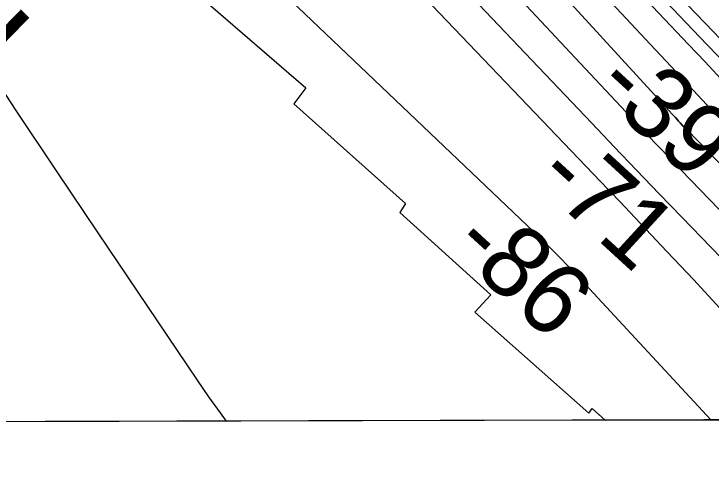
# Model space of a CAD drawing. Extents: x 3355677 to 3393573, y 612928 to 638357.
# Drawn here: x 3377478 to 3378130, y 618312 to 618740 of the extents above; entities that cross this region are included whole.
import ezdxf

# ---------------------------------------------------------------- set-up
doc = ezdxf.new("R2010")
doc.units = 0
for name, color, linetype in [('V-GRID-FRAM', 7, 'Continuous'), ('V-RIVR-EDGE', 7, 'Continuous'), ('V-RIVR-RANG', 7, 'Continuous'), ('V-RRAP-RVMT', 7, 'Continuous'), ('V-TOPO-DPTH', 7, 'Continuous'), ('V-TOPO-GNAM-IDEN', 7, 'Continuous'), ('V-TOPO-MAJR', 7, 'Continuous'), ('V-TOPO-MINR', 7, 'Continuous')]:
    doc.layers.add(name, color=color, linetype=linetype)

msp = doc.modelspace()

# ---------------------------------------------------------------- linework, layer by layer
at = {"layer": 'V-GRID-FRAM'}
msp.add_lwpolyline([(3359767.89, 636495.86), (3391341.63, 636578.52), (3391397.17, 618394.77), (3359807.56, 618312.07), (3359767.89, 636495.86)], dxfattribs=at)
at = {"layer": 'V-RIVR-EDGE'}
msp.add_spline([(3378516.49, 618361.05), (3378507.6, 618370.69), (3378490.73, 618386.23), (3378471.74, 618402.14), (3378446.08, 618427.92), (3378423.59, 618453.7), (3378402.15, 618477.72), (3378364.89, 618515.51), (3378349.43, 618530.35), (3378342.04, 618535.3), (3378334.65, 618539.2), (3378327.62, 618546.97), (3378322.71, 618554.38), (3378318.84, 618559.67), (3378306.54, 618572.39), (3378288.96, 618586.53), (3378281.23, 618596.41), (3378275.96, 618603.83), (3378258.04, 618621.84), (3378254.18, 618629.96), (3378247.86, 618638.78), (3378236.96, 618650.79), (3378233.81, 618657.14), (3378231.35, 618661.38), (3378222.57, 618670.56), (3378197.97, 618699.87), (3378183.21, 618714), (3378173.72, 618726.71), (3378162.47, 618734.49), (3378158.95, 618737.67), (3378158.61, 618741.54), (3378158.26, 618744.72), (3378155.81, 618749.66), (3378152.29, 618753.19), (3378146.31, 618755.67), (3378143.5, 618758.85), (3378140, 618769.43), (3378130.53, 618786.72), (3378121.05, 618799.43), (3378116.48, 618802.96), (3378111.54, 618803.33), (3378106.96, 618803.69), (3378107.68, 618808.27), (3378105.22, 618811.8), (3378096.08, 618818.87), (3378090.1, 618823.82), (3378078.84, 618830.54), (3378077.08, 618832.66), (3378071.83, 618844.3), (3378067.97, 618853.12), (3378067.98, 618856.29), (3378066.58, 618858.76), (3378058.13, 618863.01), (3378052.16, 618871.83), (3378044.1, 618888.77), (3378037.43, 618898.65), (3378027.59, 618911.01), (3378012.81, 618918.45), (3378000.84, 618924.11), (3377993.11, 618932.59), (3377988.55, 618941.06), (3377985.4, 618949.52), (3377982.24, 618954.46), (3377974.51, 618963.29), (3377969.24, 618967.89), (3377966.79, 618973.88), (3377960.81, 618977.77), (3377955.52, 618978.84), (3377954.83, 618983.07), (3377951.31, 618985.9), (3377937.58, 618991.22), (3377933.72, 618995.46), (3377918.25, 619012.76), (3377900.33, 619032.19), (3377899.99, 619037.47), (3377897.54, 619041.71), (3377893.67, 619045.59), (3377886.27, 619044.91), (3377882.39, 619044.92), (3377878.87, 619047.39), (3377875.72, 619053.74), (3377866.93, 619063.28), (3377843.02, 619083.78), (3377840.22, 619089.42), (3377839.18, 619096.12), (3377836.71, 619097.89), (3377833.19, 619098.25), (3377832.49, 619100.01), (3377831.44, 619103.89), (3377828.98, 619106.01), (3377820.18, 619110.97), (3377809.64, 619121.21), (3377795.58, 619135.69), (3377778.71, 619154.76), (3377773.79, 619160.41), (3377758.67, 619171.37), (3377751.64, 619178.79), (3377734.41, 619195.04), (3377715.08, 619215.53), (3377698.93, 619236.36), (3377689.44, 619246.6), (3377686.28, 619253.66), (3377675.73, 619259.67), (3377669.05, 619265.33), (3377666.24, 619269.92), (3377662.02, 619272.39), (3377656.38, 619274.17), (3377649.7, 619279.47), (3377628.6, 619296.08), (3377619.46, 619304.56), (3377610.32, 619314.45), (3377594.85, 619326.47), (3377585.71, 619336.01), (3377577.62, 619344.49), (3377561.44, 619355.45), (3377551.95, 619364.63), (3377544.22, 619374.17), (3377540.72, 619384.04), (3377539.32, 619385.81), (3377536.15, 619386.87), (3377528.75, 619389.01), (3377525.59, 619391.83), (3377523.49, 619398.53), (3377519.99, 619409.11), (3377509.1, 619421.12), (3377504.18, 619425.71), (3377489.74, 619431.04), (3377482.35, 619435.28), (3377478.49, 619440.93), (3377476.38, 619443.05), (3377471.46, 619446.94), (3377465.14, 619455.41), (3377463.39, 619460), (3377454.25, 619470.59), (3377432.47, 619495.66), (3377419.12, 619513.31), (3377396.28, 619540.15), (3377376.96, 619562.4), (3377360.09, 619581.12), (3377353.41, 619589.94), (3377348.5, 619598.76), (3377341.83, 619607.59), (3377323.55, 619623.49), (3377313.35, 619633.38), (3377305.61, 619638.33), (3377297.52, 619644.7), (3377297.53, 619647.87), (3377297.54, 619650.69), (3377294.03, 619656.69), (3377285.24, 619666.58), (3377279.28, 619677.16), (3377274.01, 619683.52), (3377265.56, 619688.47), (3377258.89, 619694.83), (3377253.62, 619705.06), (3377251.89, 619714.93), (3377248.03, 619720.93), (3377245.57, 619724.46), (3377241.7, 619727.64), (3377232.89, 619728.37), (3377223.38, 619730.86), (3377212.47, 619733.35), (3377204.37, 619737.6), (3377200.86, 619740.08), (3377195.22, 619741.15), (3377185.71, 619741.17), (3377172.33, 619748.61), (3377155.8, 619761.33), (3377143.16, 619778.28), (3377132.62, 619792.4), (3377131.93, 619797.33), (3377130.18, 619802.27), (3377123.51, 619811.1), (3377116.49, 619822.04), (3377110.17, 619832.98), (3377098.6, 619854.85), (3377095.09, 619862.97), (3377087.73, 619876.73), (3377081.41, 619884.85), (3377075.78, 619891.2), (3377063.5, 619909.91), (3377063.15, 619913.08), (3377058.59, 619921.55), (3377041.74, 619947.67), (3377035.78, 619957.9), (3377024.88, 619970.26), (3377017.51, 619982.26), (3377008.73, 619991.09), (3377000.99, 619999.22), (3376998.89, 620003.1), (3376997.85, 620008.39), (3376993.28, 620014.39), (3376981.69, 620029.57), (3376966.57, 620041.59), (3376947.93, 620056.08), (3376931.04, 620066.69), (3376914.5, 620075.54), (3376905.71, 620081.91), (3376896.22, 620095.67), (3376889.56, 620109.08), (3376877.63, 620128.14), (3376863.24, 620153.19), (3376850.61, 620175.78), (3376840.44, 620195.18), (3376834.13, 620206.12), (3376830.62, 620213.88), (3376827.11, 620219.88), (3376766.3, 620280.64), (3376733.96, 620311.73), (3376710.76, 620332.22), (3376680.51, 620356.61), (3376664.69, 620368.98), (3376652.37, 620376.06), (3376623.52, 620393.4), (3376605.58, 620405.78), (3376585.52, 620418.86), (3376578.14, 620424.17), (3376571.8, 620428.06), (3376565.46, 620427.02), (3376541.18, 620440.12), (3376536.96, 620446.47), (3376535.22, 620453.17), (3376537.71, 620461.97), (3376537.72, 620466.2), (3376535.61, 620469.03), (3376529.98, 620470.8), (3376523.63, 620470.11), (3376520.11, 620471.53), (3376509.21, 620481.07), (3376501.13, 620489.55), (3376495.52, 620499.78), (3376489.55, 620510.72), (3376487.1, 620514.95), (3376486.05, 620518.13), (3376484.29, 620520.6), (3376464.95, 620537.91), (3376449.83, 620547.47), (3376433.64, 620556.31), (3376408.32, 620577.17), (3376393.54, 620585.66), (3376376.29, 620593.81), (3376351.66, 620606.2), (3376335.11, 620613.29), (3376324.56, 620620.01), (3376307.31, 620625.34), (3376296.04, 620630.65), (3376270.36, 620648.34), (3376252.78, 620662.12), (3376242.94, 620672.72), (3376238.01, 620675.9), (3376233.43, 620676.62), (3376229.56, 620679.09), (3376210.93, 620695.35), (3376192.64, 620709.84), (3376157.47, 620736.71), (3376139.88, 620750.14), (3376127.93, 620761.8), (3376118.44, 620769.58), (3376106.12, 620776.3), (3376072.01, 620806.34), (3376048.47, 620834.23), (3376004.89, 620878.04), (3375983.1, 620902.76), (3375960.97, 620929.59), (3375953.95, 620939.83), (3375949.03, 620948.3), (3375944.83, 620957.82), (3375936.05, 620971.59), (3375912.87, 621001.6), (3375906.89, 621006.9), (3375899.52, 621016.43), (3375896.01, 621023.48), (3375881.26, 621042.55), (3375856.32, 621075.38), (3375835.59, 621097.28), (3375809.57, 621122.72), (3375786.01, 621142.15), (3375742.74, 621169.75), (3375706.5, 621193.09), (3375654.8, 621233.74), (3375605.57, 621273.68), (3375571.82, 621307.24), (3375559.88, 621321.37), (3375554.61, 621330.89), (3375550.75, 621336.89), (3375547.94, 621339.72), (3375541.25, 621342.56), (3375536.33, 621345.74), (3375533.51, 621347.86), (3375528.24, 621352.81), (3375524.03, 621359.16), (3375521.22, 621361.99), (3375518.76, 621365.16), (3375514.54, 621369.76), (3375499.05, 621375.43), (3375478.63, 621382.53), (3375451.52, 621393.17), (3375434.62, 621398.5), (3375424.77, 621404.51), (3375412.44, 621407.36), (3375405.76, 621410.55), (3375395.2, 621414.45), (3375385.69, 621417.29), (3375374.07, 621420.49), (3375363.5, 621420.87), (3375351.51, 621419.14), (3375336.69, 621411.07), (3375326.11, 621405.81), (3375315.54, 621405.48), (3375306.73, 621408.33), (3375297.58, 621412.93), (3375285.62, 621419.3), (3375281.41, 621425.65), (3375276.14, 621431.66), (3375271.91, 621433.78), (3375264.16, 621435.21), (3375259.93, 621435.22), (3375254.65, 621435.24), (3375251.48, 621435.24), (3375245.49, 621436.31), (3375239.86, 621437.74), (3375215.21, 621444.49), (3375187.39, 621452.67), (3375156.75, 621461.2), (3375150.77, 621464.74), (3375147.25, 621465.8), (3375142.67, 621466.87), (3375137.39, 621467.94), (3375132.1, 621468.31), (3375129.64, 621468.32), (3375105.35, 621477.18), (3375084.93, 621485.69), (3375080.36, 621489.23), (3375075.08, 621491.35), (3375067.33, 621492.43), (3375058.88, 621497.03), (3375037.06, 621506.95), (3374951.91, 621556.5), (3374890.69, 621595.76), (3374838.99, 621635), (3374815.41, 621649.51), (3374801.34, 621657.65)], degree=3, dxfattribs=at)
at = {"layer": 'V-RRAP-RVMT'}
for p, q in [((3377650.96, 618757.19), (3377750.73, 618670.87)), ((3377750.73, 618670.87), (3377739.48, 618655.88)), ((3377739.48, 618655.88), (3377843.97, 618562.35)), ((3377843.97, 618562.35), (3377838.68, 618553.91)), ((3377838.68, 618553.91), (3377923.74, 618477.13)), ((3377923.74, 618477.13), (3377908.82, 618460.92)), ((3377908.82, 618460.92), (3378015.57, 618366.23)), ((3378015.57, 618366.23), (3378018.72, 618370.53)), ((3378018.72, 618370.53), (3378030.91, 618359.78)), ((3378030.91, 618359.78), (3378546.23, 618361.13))]:
    msp.add_line(p, q, dxfattribs=at)
at = {"layer": 'V-TOPO-DPTH'}
for points in [[(3378476.02, 618360.94), (3378448.01, 618390.37), (3378375.02, 618467.18), (3378302.07, 618544.02), (3378204.39, 618646.98), (3378180.3, 618672.37), (3378156.2, 618697.74), (3378132.09, 618723.11), (3378107.97, 618748.46), (3378083.82, 618773.79), (3378059.62, 618799.07), (3378035.36, 618824.29), (3378011.06, 618849.47), (3377654.1, 619218.36), (3377630.45, 619242.73), (3377606.74, 619267.05), (3377582.95, 619291.29), (3377559.11, 619315.48), (3377535.23, 619339.63), (3377511.35, 619363.79), (3377487.48, 619387.94), (3377463.6, 619412.1), (3377132.12, 619747.52), (3377122.42, 619757.43)], [(3378369.48, 618360.66), (3378107.77, 618630.99), (3378105.54, 618633.31), (3378103.3, 618635.62), (3378100.96, 618638.07), (3378099.49, 618639.64), (3378098.71, 618640.5), (3378096.55, 618642.88), (3378093.62, 618646.11), (3378090.67, 618649.34), (3377711.84, 619063.27), (3377687.62, 619089.53), (3377663.27, 619115.66), (3377638.71, 619141.61), (3377614.03, 619167.43), (3377577.27, 619205.59), (3377570.84, 619212.22), (3377564.39, 619218.82), (3377557.9, 619225.39), (3377551.37, 619231.92), (3377089.65, 619691.99)], [(3377089.65, 619691.99), (3377551.37, 619231.92), (3377557.9, 619225.39), (3377564.39, 619218.82), (3377570.84, 619212.22), (3377577.27, 619205.59), (3377614.03, 619167.43), (3377638.71, 619141.61), (3377663.27, 619115.66), (3377687.62, 619089.53), (3377711.84, 619063.27), (3378090.67, 618649.34), (3378093.62, 618646.11), (3378096.55, 618642.88), (3378098.71, 618640.5), (3378099.49, 618639.64), (3378100.96, 618638.07), (3378103.3, 618635.62), (3378105.54, 618633.31), (3378107.77, 618630.99), (3378369.48, 618360.66)], [(3377298.46, 619514.44), (3377550.44, 619262.16), (3377564.24, 619248.26), (3377578, 619234.32), (3377591.68, 619220.31), (3377605.31, 619206.25), (3377683.76, 619124.9), (3377736.44, 619070), (3377788.94, 619014.93), (3377841.17, 618959.59), (3377893.21, 618904.09), (3378072.94, 618711.43), (3378097.07, 618685.6), (3378121.23, 618659.8), (3378145.43, 618634.04), (3378169.66, 618608.3), (3378323.13, 618445.51), (3378403.35, 618360.75)], [(3377298.46, 619514.44), (3377550.44, 619262.16), (3377564.24, 619248.26), (3377578, 619234.32), (3377591.68, 619220.31), (3377605.31, 619206.25), (3377683.76, 619124.9), (3377736.44, 619070), (3377788.94, 619014.93), (3377841.17, 618959.59), (3377893.21, 618904.09), (3378072.94, 618711.43), (3378097.07, 618685.6), (3378121.23, 618659.8), (3378145.43, 618634.04), (3378169.66, 618608.3), (3378323.13, 618445.51), (3378403.35, 618360.75), (3378369.48, 618360.66)], [(3377424.98, 619418.97), (3377480.69, 619362.78), (3377549.54, 619293.5), (3377570.85, 619271.97), (3377592.09, 619250.38), (3377613.25, 619228.7), (3377634.34, 619206.95), (3377810.89, 619024.16), (3377865.93, 618966.98), (3377920.83, 618909.68), (3377975.55, 618852.2), (3378030.14, 618794.6), (3378108.77, 618711.35), (3378123.95, 618695.28), (3378139.13, 618679.22), (3378154.32, 618663.17), (3378169.52, 618647.12), (3378440.7, 618360.85), (3378476.02, 618360.94)], [(3378403.35, 618360.75), (3378440.7, 618360.85), (3378169.52, 618647.12), (3378154.32, 618663.17), (3378139.13, 618679.22), (3378123.95, 618695.28), (3378108.77, 618711.35), (3378030.14, 618794.6), (3377975.55, 618852.2), (3377920.83, 618909.68), (3377865.93, 618966.98), (3377810.89, 619024.16), (3377634.34, 619206.95), (3377613.25, 619228.7), (3377592.09, 619250.38), (3377570.85, 619271.97), (3377549.54, 619293.5), (3377480.69, 619362.78), (3377424.98, 619418.97)], [(3378514.15, 618361.04), (3378476.02, 618360.94), (3378448.01, 618390.37), (3378375.02, 618467.18), (3378302.07, 618544.02), (3378204.39, 618646.98), (3378180.3, 618672.37), (3378156.2, 618697.74), (3378132.09, 618723.11), (3378107.97, 618748.46), (3378083.82, 618773.79), (3378059.62, 618799.07), (3378035.36, 618824.29), (3378011.06, 618849.47), (3377654.1, 619218.36), (3377630.45, 619242.73), (3377606.74, 619267.05), (3377582.95, 619291.29), (3377559.11, 619315.48), (3377535.23, 619339.63), (3377511.35, 619363.79), (3377487.48, 619387.94), (3377463.6, 619412.1)], [(3378369.48, 618360.66), (3376767.5, 618356.47), (3376734.14, 618394.29), (3376681.43, 618455.32), (3376541.08, 618620.35)]]:
    msp.add_lwpolyline(points, dxfattribs=at)
at = {"layer": 'V-TOPO-MAJR'}
msp.add_lwpolyline([(3378327.08, 618360.55), (3378306.54, 618381.76), (3378101.82, 618593.73), (3378091.23, 618604.75), (3378080.67, 618615.79), (3378070.15, 618626.88), (3378059.68, 618638.01), (3378007.39, 618693.75), (3377970.91, 618732.87), (3377934.57, 618772.13), (3377898.47, 618811.6), (3377862.52, 618851.21), (3377565.04, 619180.83), (3377556.37, 619190.33), (3377547.62, 619199.75), (3377538.75, 619209.06), (3377529.8, 619218.3), (3377520.76, 619227.44), (3377511.65, 619236.51), (3377502.44, 619245.5), (3377493.18, 619254.42), (3377066.6, 619660.87)], dxfattribs=at)
at = {"layer": 'V-TOPO-MINR'}
for points in [[(3378458.22, 618360.9), (3378169.4, 618665.56), (3378158.53, 618677.02), (3378147.67, 618688.49), (3378136.8, 618699.95), (3378125.94, 618711.41), (3378068.6, 618771.89), (3378029.01, 618813.54), (3377989.33, 618855.11), (3377949.53, 618896.56), (3377909.65, 618937.94), (3377649.23, 619207.33), (3377624.32, 619233.01), (3377599.33, 619258.63), (3377574.25, 619284.15), (3377549.11, 619309.61), (3377519.93, 619339.05), (3377480.17, 619379.2), (3377440.45, 619419.39), (3377400.77, 619459.63), (3377361.13, 619499.9), (3377132.43, 619732.5), (3377119.18, 619746.11), (3377106.02, 619759.8)], [(3378476.02, 618360.94), (3378448.01, 618390.37), (3378375.02, 618467.18), (3378302.07, 618544.02), (3378204.39, 618646.98), (3378180.3, 618672.37), (3378156.2, 618697.74), (3378132.09, 618723.11), (3378107.97, 618748.46), (3378083.82, 618773.79), (3378059.62, 618799.07), (3378035.36, 618824.29), (3378011.06, 618849.47), (3377654.1, 619218.36), (3377630.45, 619242.73), (3377606.74, 619267.05), (3377582.95, 619291.29), (3377559.11, 619315.48), (3377535.23, 619339.63), (3377511.35, 619363.79), (3377487.48, 619387.94), (3377463.6, 619412.1), (3377132.12, 619747.52), (3377122.42, 619757.43)], [(3377089.65, 619691.99), (3377551.37, 619231.92), (3377557.9, 619225.39), (3377564.39, 619218.82), (3377570.84, 619212.22), (3377577.27, 619205.59), (3377614.03, 619167.43), (3377638.71, 619141.61), (3377663.27, 619115.66), (3377687.62, 619089.53), (3377711.84, 619063.27), (3378090.67, 618649.34), (3378093.62, 618646.11), (3378096.55, 618642.88), (3378098.71, 618640.5), (3378099.49, 618639.64), (3378100.96, 618638.07), (3378103.3, 618635.62), (3378105.54, 618633.31), (3378107.77, 618630.99), (3378369.48, 618360.66)], [(3378285.58, 618360.44), (3378102.38, 618549.75), (3378081.26, 618571.64), (3378060.19, 618593.57), (3378039.19, 618615.57), (3378018.23, 618637.61), (3377875.33, 618788.39), (3377815.63, 618851.07), (3377755.73, 618913.54), (3377695.51, 618975.72), (3377635.09, 619037.7), (3377543.24, 619131.42), (3377528.46, 619146.26), (3377513.53, 619160.94), (3377498.35, 619175.36), (3377483.02, 619189.63), (3377060.84, 619575.92)], [(3378403.35, 618360.75), (3378323.13, 618445.51), (3378169.66, 618608.3), (3378145.43, 618634.04), (3378121.23, 618659.8), (3378097.07, 618685.6), (3378072.94, 618711.43), (3377893.21, 618904.09), (3377841.17, 618959.59), (3377788.94, 619014.93), (3377736.44, 619070), (3377683.76, 619124.9), (3377605.31, 619206.25), (3377591.68, 619220.31), (3377578, 619234.32), (3377564.24, 619248.26), (3377550.44, 619262.16), (3377298.46, 619514.44)], [(3378440.7, 618360.85), (3378169.52, 618647.12), (3378154.32, 618663.17), (3378139.13, 618679.22), (3378123.95, 618695.28), (3378108.77, 618711.35), (3378030.14, 618794.6), (3377975.55, 618852.2), (3377920.83, 618909.68), (3377865.93, 618966.98), (3377810.89, 619024.16), (3377634.34, 619206.95), (3377613.25, 619228.7), (3377592.09, 619250.38), (3377570.85, 619271.97), (3377549.54, 619293.5), (3377480.69, 619362.78), (3377424.98, 619418.97)], [(3378232.9, 618360.31), (3378187.01, 618411.1), (3378162.61, 618437.92), (3378138.09, 618464.64), (3378113.4, 618491.19), (3378088.59, 618517.64), (3378044.11, 618564.72), (3378041.45, 618567.54), (3378038.78, 618570.36), (3378036.1, 618573.16), (3378033.43, 618575.97), (3377595.69, 619034.11), (3377578.85, 619051.63), (3377561.95, 619069.09), (3377544.95, 619086.46), (3377527.89, 619103.77), (3377501.56, 619130.33), (3377497.59, 619134.28), (3377493.59, 619138.2), (3377489.54, 619142.07), (3377485.45, 619145.9), (3377423.89, 619202.93)], [(3378129.59, 618360.04), (3378008.26, 618491.17), (3377997.52, 618502.56), (3377986.63, 618513.82), (3377975.53, 618524.87), (3377964.3, 618535.77), (3377437.73, 619037.2)], [(3377441.77, 618706.89), (3377479.7, 618649.42), (3377517.89, 618592.12), (3377556.24, 618534.94), (3377649.22, 618396.99), (3377659.83, 618381.62), (3377670.66, 618366.42), (3377676.31, 618358.85)]]:
    msp.add_lwpolyline(points, dxfattribs=at)

# ---------------------------------------------------------------- texts
at = {"layer": 'V-RIVR-RANG'}
for s, p in [('-39', (3378018.4, 618668.77)), ('-71', (3377963.06, 618583.83)), ('-86', (3377884.59, 618520.11))]:
    msp.add_text(s, height=67, rotation=317.47175, dxfattribs=at).set_placement(p)
at = {"layer": 'V-TOPO-GNAM-IDEN'}
msp.add_text('GEISMAR', height=100, rotation=45.79144, dxfattribs=at).set_placement((3377361.53, 618601.97))

doc.saveas('drawing.dxf')
